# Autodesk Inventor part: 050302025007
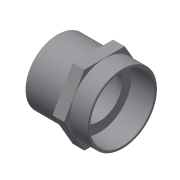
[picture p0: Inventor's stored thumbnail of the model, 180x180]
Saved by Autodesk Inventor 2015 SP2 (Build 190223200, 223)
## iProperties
Created: 2017-10
Part Number: 050302025007
Material: Generic
Description: PLASSON ADAPTOR SOCKET M.F. 25-3/4" CEM-THR
Document SubType Name: Modeling
Designer: KIM
Density: 1 g/cm^3
Appearance: Default
Author: KIM
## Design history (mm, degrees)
derived "050302.ipt"
feature "Solid1::050302.ipt"
tag "TaggingFeature1"
body "Solid1"
other parameters: "d0" = 46, "d3" = 24.117, "d4" = 17.5, "d6" = 18, "d8" = 28.75, "d13" = 0, "d14" = 0.25, "d16" = 12, "d17" = 19, "d18" = 21.6, "d19" = 25, "d_" = 25, "G_" = 24.117, "B_" = 12, "L_" = 19, "lt_" = 18, "H_" = 46
